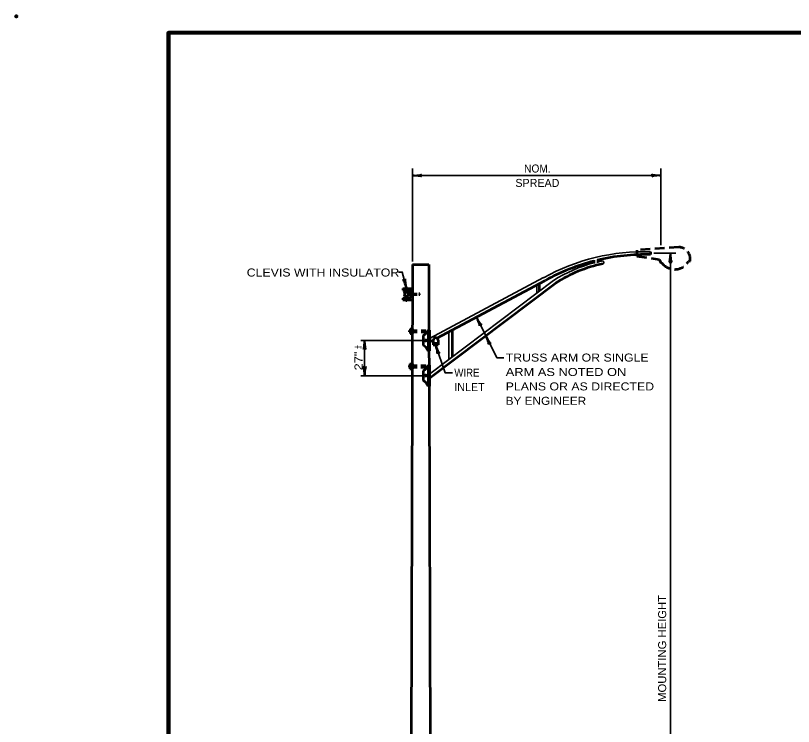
# Model space of a CAD drawing. Extents: x -34 to 821, y -14 to 530.
# Drawn here: x -34.1 to 257.5, y 264 to 530.3 of the extents above; entities that cross this region are included whole.
import ezdxf
from ezdxf.enums import TextEntityAlignment as Align

# ---------------------------------------------------------------- set-up
doc = ezdxf.new("R2010")
doc.units = 0
doc.header["$LTSCALE"] = 1.2
doc.header["$PDMODE"] = 32
doc.header["$PDSIZE"] = 0.6
doc.linetypes.add('MEDIUM_DASHED', pattern=[4.5, 3, -1.5])
doc.linetypes.add('SHORT_DASHED', pattern=[2.7, 1.5, -1.2])
doc.layers.add('1', color=7, linetype='Continuous', lineweight=53)

msp = doc.modelspace()

# ---------------------------------------------------------------- linework, layer by layer
at = {"layer": '1', "lineweight": 35}
for p, q in [((114.726, 438.221), (114.726, 473.021)), ((207.786, 444.272), (207.786, 473.021)), ((114.726, 470.367), (207.786, 470.367)), ((205.065, 441.305), (213.324, 441.305)), ((211.368, 126.405), (211.368, 441.305)), ((121.067, 409.385), (163.787, 432.113)), ((121.139, 396.089), (167.507, 431.033)), ((161.291, 429.401), (161.291, 426.353)), ((128.339, 412.049), (128.339, 401.729)), ((118.138, 408.61), (95.256, 408.61)), ((96.715, 395.37), (96.715, 408.61)), ((146.23, 402.122), (148.844, 402.122)), ((118.138, 395.37), (95.256, 395.37))]:
    msp.add_line(p, q, dxfattribs=at)
at = {"layer": '1'}
for p, q in [((203.877, 441.803), (203.852, 440.751)), ((114.726, 437.021), (113.526, 74.621)), ((114.726, 437.021), (120.726, 437.021)), ((120.726, 437.021), (120.807, 412.498)), ((121.139, 394.577), (168.227, 430.073)), ((123.799, 409.469), (164.363, 431.033)), ((162.203, 429.881), (162.203, 427.025)), ((111.029, 428.035), (114.629, 428.035)), ((111.029, 428.035), (111.029, 427.435)), ((111.029, 427.435), (114.029, 427.435)), ((111.629, 426.835), (113.129, 426.835)), ((111.629, 426.835), (111.629, 426.685)), ((111.629, 426.685), (113.129, 426.685)), ((112.229, 427.435), (112.229, 426.835)), ((112.529, 427.435), (112.529, 426.835)), ((113.129, 426.835), (113.129, 426.685)), ((114.029, 427.435), (114.029, 424.435)), ((114.629, 428.035), (114.629, 423.835)), ((111.029, 424.435), (114.029, 424.435)), ((111.029, 424.435), (111.029, 423.835)), ((111.029, 423.835), (114.629, 423.835)), ((111.629, 425.185), (113.129, 425.185)), ((111.629, 425.185), (111.629, 425.035)), ((111.629, 425.035), (113.129, 425.035)), ((112.229, 425.035), (112.229, 424.435)), ((112.229, 423.835), (112.229, 423.535)), ((112.229, 423.535), (112.529, 423.535)), ((112.529, 425.035), (112.529, 424.435)), ((112.529, 423.835), (112.529, 423.535)), ((113.129, 425.185), (113.129, 425.035)), ((113.454, 412.365), (113.754, 412.365)), ((113.454, 412.365), (113.454, 411.765)), ((113.454, 411.765), (113.754, 411.765)), ((113.754, 412.965), (113.754, 411.165)), ((113.754, 412.965), (114.654, 412.965)), ((113.754, 411.165), (114.654, 411.165)), ((114.654, 412.965), (114.654, 411.165)), ((120.486, 412.498), (120.486, 404.698)), ((121.086, 412.498), (120.486, 412.498)), ((121.086, 412.498), (121.086, 404.698)), ((129.539, 412.529), (129.539, 402.425)), ((118.686, 410.398), (118.686, 406.798)), ((121.086, 408.027), (122.463, 408.759)), ((122.463, 408.74), (122.463, 406.94)), ((124.263, 408.74), (124.263, 406.94)), ((122.463, 407.54), (124.263, 407.54)), ((122.463, 406.94), (124.263, 406.94)), ((121.086, 404.698), (120.486, 404.698)), ((120.833, 404.698), (120.851, 399.319)), ((113.709, 399.774), (113.709, 397.974)), ((113.709, 399.774), (114.609, 399.774)), ((114.609, 399.774), (114.609, 397.974)), ((113.409, 399.174), (113.709, 399.174)), ((113.409, 399.174), (113.409, 398.574)), ((113.409, 398.574), (113.709, 398.574)), ((113.709, 397.974), (114.609, 397.974)), ((118.686, 397.219), (118.686, 393.619)), ((120.486, 399.319), (120.486, 391.519)), ((121.086, 399.319), (120.486, 399.319)), ((121.086, 399.319), (121.086, 391.519)), ((121.086, 391.519), (120.486, 391.519)), ((120.877, 391.519), (121.926, 74.621))]:
    msp.add_line(p, q, dxfattribs=at)
at = {"layer": '1', "lineweight": 40}
for p, q in [((182.771, 438.641), (182.771, 437.393)), ((183.971, 438.953), (183.971, 437.705))]:
    msp.add_line(p, q, dxfattribs=at)
at = {"layer": '1', "linetype": 'MEDIUM_DASHED'}
for p, q in [((207.879, 437.591), (208.184, 437.613)), ((218.145, 438.316), (218.751, 438.359))]:
    msp.add_line(p, q, dxfattribs=at)
at = {"layer": '1', "linetype": 'SHORT_DASHED'}
for p, q in [((114.629, 426.085), (117.029, 426.085)), ((114.629, 425.785), (117.029, 425.785)), ((114.654, 412.365), (120.43, 412.365)), ((114.654, 411.765), (120.105, 411.765)), ((114.609, 399.174), (120.424, 399.174)), ((114.609, 398.574), (120.096, 398.574))]:
    msp.add_line(p, q, dxfattribs=at)
at = {"layer": '1', "lineweight": 158}
msp.add_lwpolyline([(814.88, 523.876), (23.18, 523.776), (23.28, -2.224)], dxfattribs=at)
at = {"layer": '1', "linetype": 'MEDIUM_DASHED'}
msp.add_lwpolyline([(214.479, 443.543), (198.783, 442.439), (198.783, 440.111), (207.183, 438.935), (207.879, 437.591)], dxfattribs=at)
at = {"layer": '1', "lineweight": 35}
for points in [[(112.355, 428.225), (110.816, 434.197), (109.376, 434.197)], [(138.667, 417.329), (142.118, 410.391), (146.23, 402.122)], [(123.31, 406.94), (126.954, 396.462), (129.7, 396.462)]]:
    msp.add_lwpolyline(points, dxfattribs=at)
at = {"layer": '1'}
for centre in [(119.584, 408.598), (119.584, 395.42)]:
    msp.add_circle(centre, 0.246, dxfattribs=at)
at = {"layer": '1', "linetype": 'MEDIUM_DASHED'}
for centre, radius, start, end in [((214.332, 439.07), 4.47, 350.72659, 88.16029), ((212.94, 441.144), 5.924, 216.5956, 331.48566)]:
    msp.add_arc(centre, radius, start, end, dxfattribs=at)
at = {"layer": '1', "lineweight": 35}
for centre, radius, start, end in [((201.469, 364.079), 77.761, 88.22597, 118.97566), ((197.099, 384.14), 55.448, 104.98386, 122.26161), ((197.099, 384.14), 55.448, 101.77153, 103.69374), ((185.859, 437.876), 0.55, 287.04383, 97.53852)]:
    msp.add_arc(centre, radius, start, end, dxfattribs=at)
at = {"layer": '1'}
for centre, radius, start, end in [((202.037, 363.011), 77.761, 88.66269, 103.43313), ((202.037, 363.011), 77.761, 104.35124, 118.97566), ((197.827, 383.174), 55.448, 102.29396, 122.26161), ((110.298, 425.935), 1.528, 330.61497, 29.38503), ((112.379, 427.895), 0.331, 25.01454, 154.98546), ((114.461, 425.935), 1.528, 150.61497, 209.38503), ((114.107, 425.935), 0.31, 104.46748, 255.53251), ((116.454, 414.132), 4.351, 300.86604, 337.93136), ((123.363, 408.679), 0.902, 3.92026, 176.07974), ((116.454, 403.063), 4.351, 22.06864, 59.13396), ((116.454, 400.954), 4.351, 300.86604, 337.93136), ((116.454, 389.885), 4.351, 22.06864, 59.13396)]:
    msp.add_arc(centre, radius, start, end, dxfattribs=at)
at = {"layer": '1', "lineweight": 40}
for centre, major_axis, ratio, start_param, end_param in [((116.035, 470.699), (-2.143, -0.187), 0.122415, 0.8963533, 3.1415927), ((116.071, 470.113), (-2.108, 0.211), 0.07063, 3.1407148, 5.41811), ((206.477, 470.036), (2.143, 0.187), 0.122415, 0.8963533, 3.1415927), ((206.441, 470.621), (2.108, -0.211), 0.07063, 3.1407148, 5.41811), ((211.114, 439.96), (0.211, 2.108), 0.07063, 3.1407148, 5.41811), ((211.114, 439.96), (0.211, 2.108), 0.07063, 3.1407148, 5.41811), ((211.7, 439.996), (-0.187, 2.143), 0.122415, 0.8963533, 3.1415927), ((211.7, 439.996), (-0.187, 2.143), 0.122415, 0.8963533, 3.1415927), ((112.265, 429.59), (-0.322, 2.094), 0.07063, 6.2823074, 8.5597026), ((111.707, 429.41), (0.716, -2.028), 0.122415, 0.8963533, 3.1415927), ((139.038, 416.012), (-0.75, 1.981), 0.07063, 3.1407148, 5.41811), ((139.038, 416.012), (-0.75, 1.981), 0.07063, 3.1407148, 5.41811), ((139.547, 416.304), (-1.122, 1.835), 0.122415, 0.8963533, 3.1415927), ((139.547, 416.304), (-1.122, 1.835), 0.122415, 0.8963533, 3.1415927), ((96.461, 407.265), (0.211, 2.108), 0.07063, 3.1407148, 5.41811), ((97.046, 407.3), (-0.187, 2.143), 0.122415, 0.8963533, 3.1415927), ((142.489, 409.074), (0.75, -1.981), 0.07063, 6.2823074, 8.5597026), ((142.998, 409.366), (-1.122, 1.835), 0.122415, 0.8963533, 3.1415927), ((123.512, 405.587), (0.493, -2.06), 0.07063, 6.2823074, 8.5597026), ((124.053, 405.812), (-0.881, 1.962), 0.122415, 0.8963533, 3.1415927), ((96.383, 396.679), (0.187, -2.143), 0.122415, 0.8963533, 3.1415927), ((96.969, 396.714), (-0.211, -2.108), 0.07063, 3.1407148, 5.41811)]:
    msp.add_ellipse(centre, major_axis=major_axis, ratio=ratio, start_param=start_param, end_param=end_param, dxfattribs=at)
at = {"layer": '1', "linetype": 'SHORT_DASHED'}
msp.add_ellipse((117.029, 425.935), major_axis=(0.405, 0), ratio=0.370014, start_param=4.712389, end_param=7.8539816, dxfattribs=at)
at = {"layer": '1'}
msp.add_point((-33.821, 529.976), dxfattribs=at)

# ---------------------------------------------------------------- texts
at = {"layer": '1', "width": 0.95}
msp.add_text('NOM.', height=3, dxfattribs=at).set_placement((161.477, 471.492), align=Align.CENTER)
at = {"layer": '1'}
msp.add_text('SPREAD', height=3, dxfattribs=at).set_placement((161.477, 466.092), align=Align.CENTER)
for s, width, p in [('CLEVIS WITH INSULATOR', 1.15, (52.538, 432.539)), ('TRUSS ARM OR SINGLE', 1.15, (149.602, 400.679)), ('WIRE', 0.9, (130.339, 395.024)), ('ARM AS NOTED ON', 1.2, (149.602, 395.279)), ('PLANS OR AS DIRECTED', 1.15, (149.602, 389.879)), ('BY ENGINEER', 1.1, (149.602, 384.479))]:
    msp.add_text(s, height=3, dxfattribs=dict(at, width=width)).set_placement(p)
for s, width, p in [('+', 0.55, (95.465, 405.334)), ('27"', 1.2, (95.925, 397.364)), ('MOUNTING HEIGHT', 1.05, (209.744, 273.237))]:
    msp.add_text(s, height=3, rotation=90, dxfattribs=dict(at, width=width)).set_placement(p)
msp.add_text('-', height=3, rotation=90, dxfattribs=at).set_placement((96.522, 405.334))
msp.add_text('INLET', height=3, dxfattribs=at).set_placement((130.339, 389.624))

doc.saveas('drawing.dxf')
